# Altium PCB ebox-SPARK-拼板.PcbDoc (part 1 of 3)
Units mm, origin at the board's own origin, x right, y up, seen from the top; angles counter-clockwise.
Board outline 102 x 90 mm, 2 copper layers (Top Layer, Bottom Layer); 141 components, 68 nets, 621 pads, 146 vias.
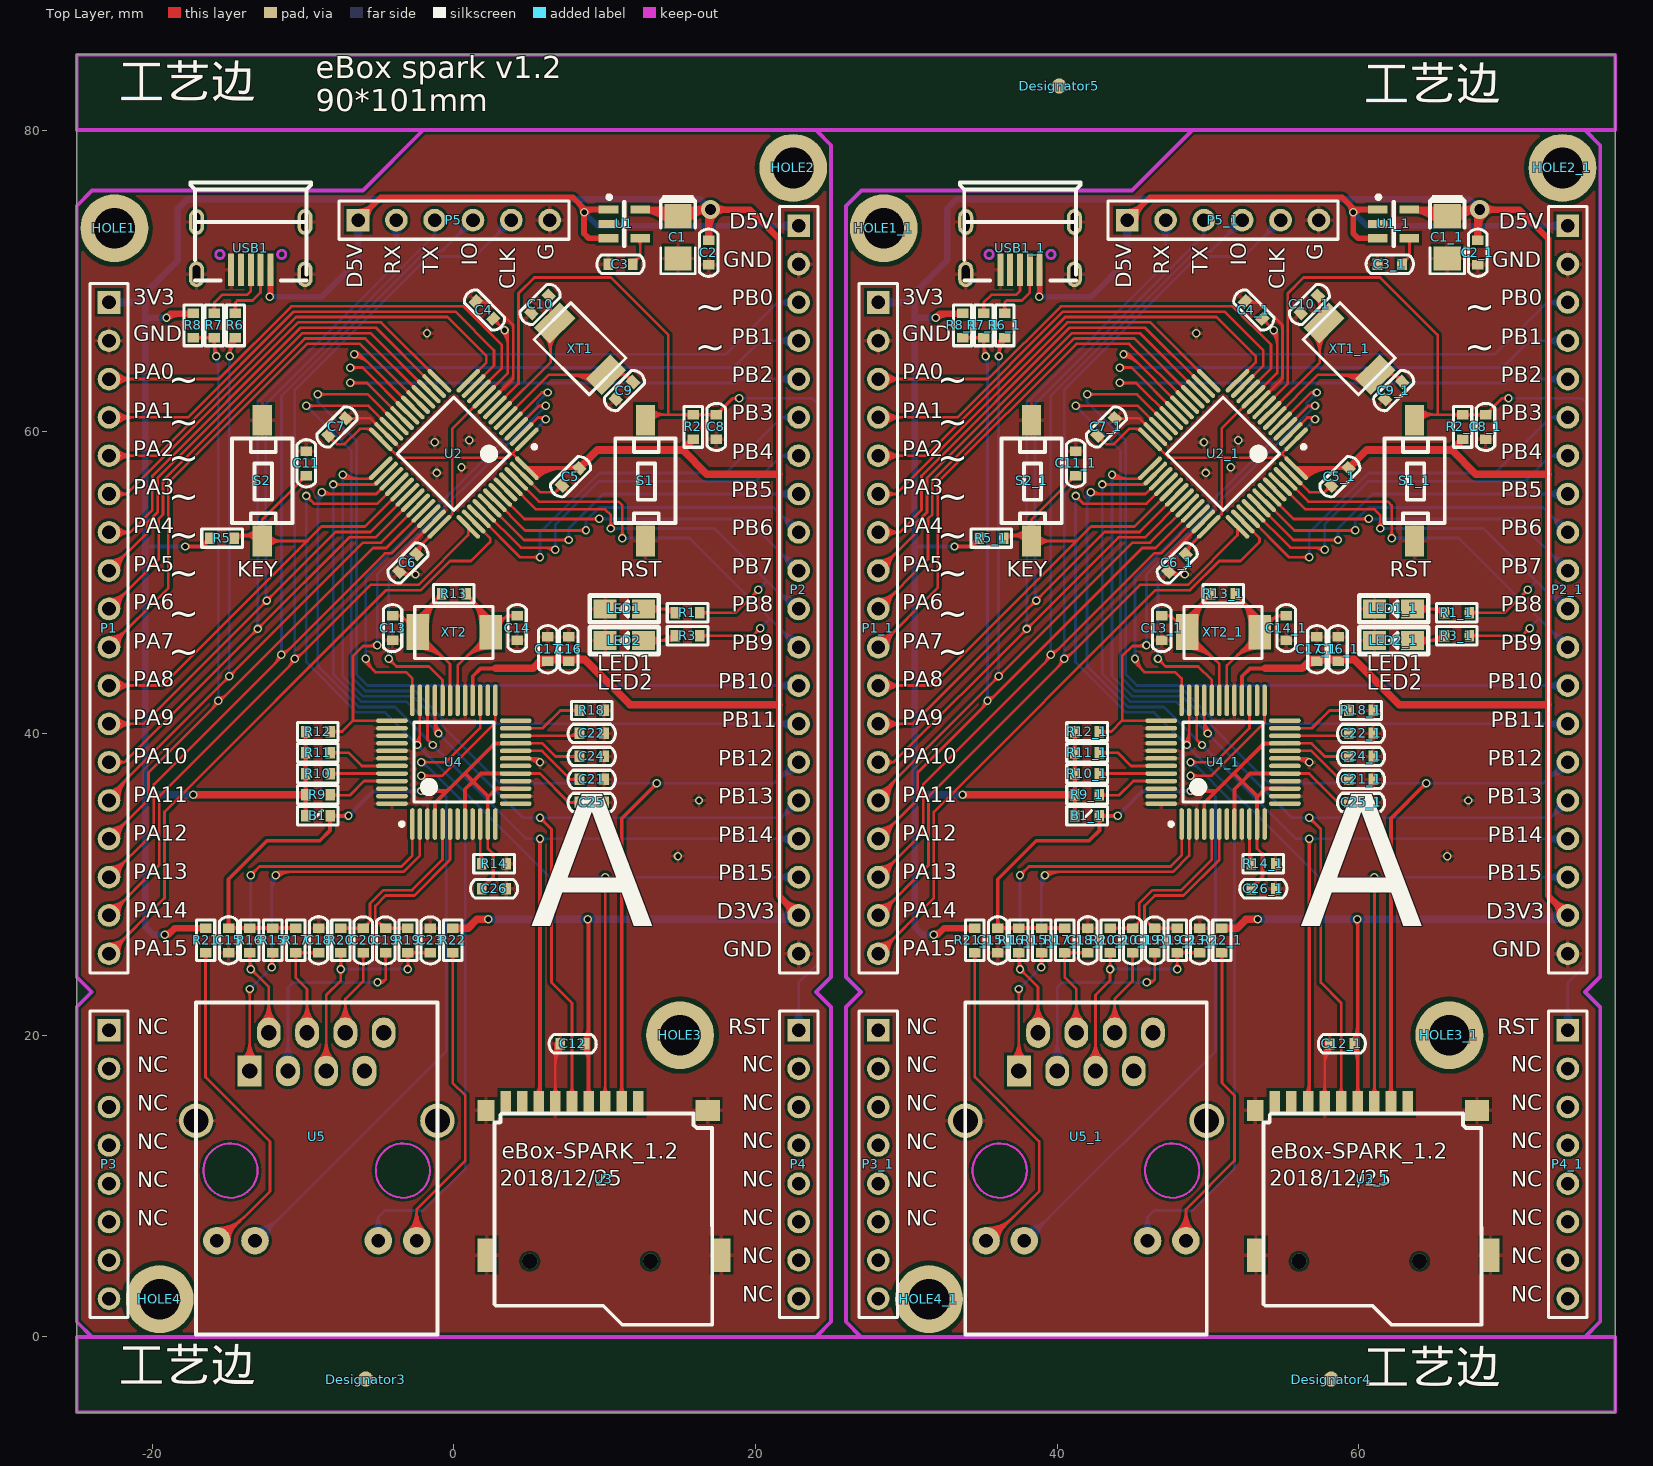
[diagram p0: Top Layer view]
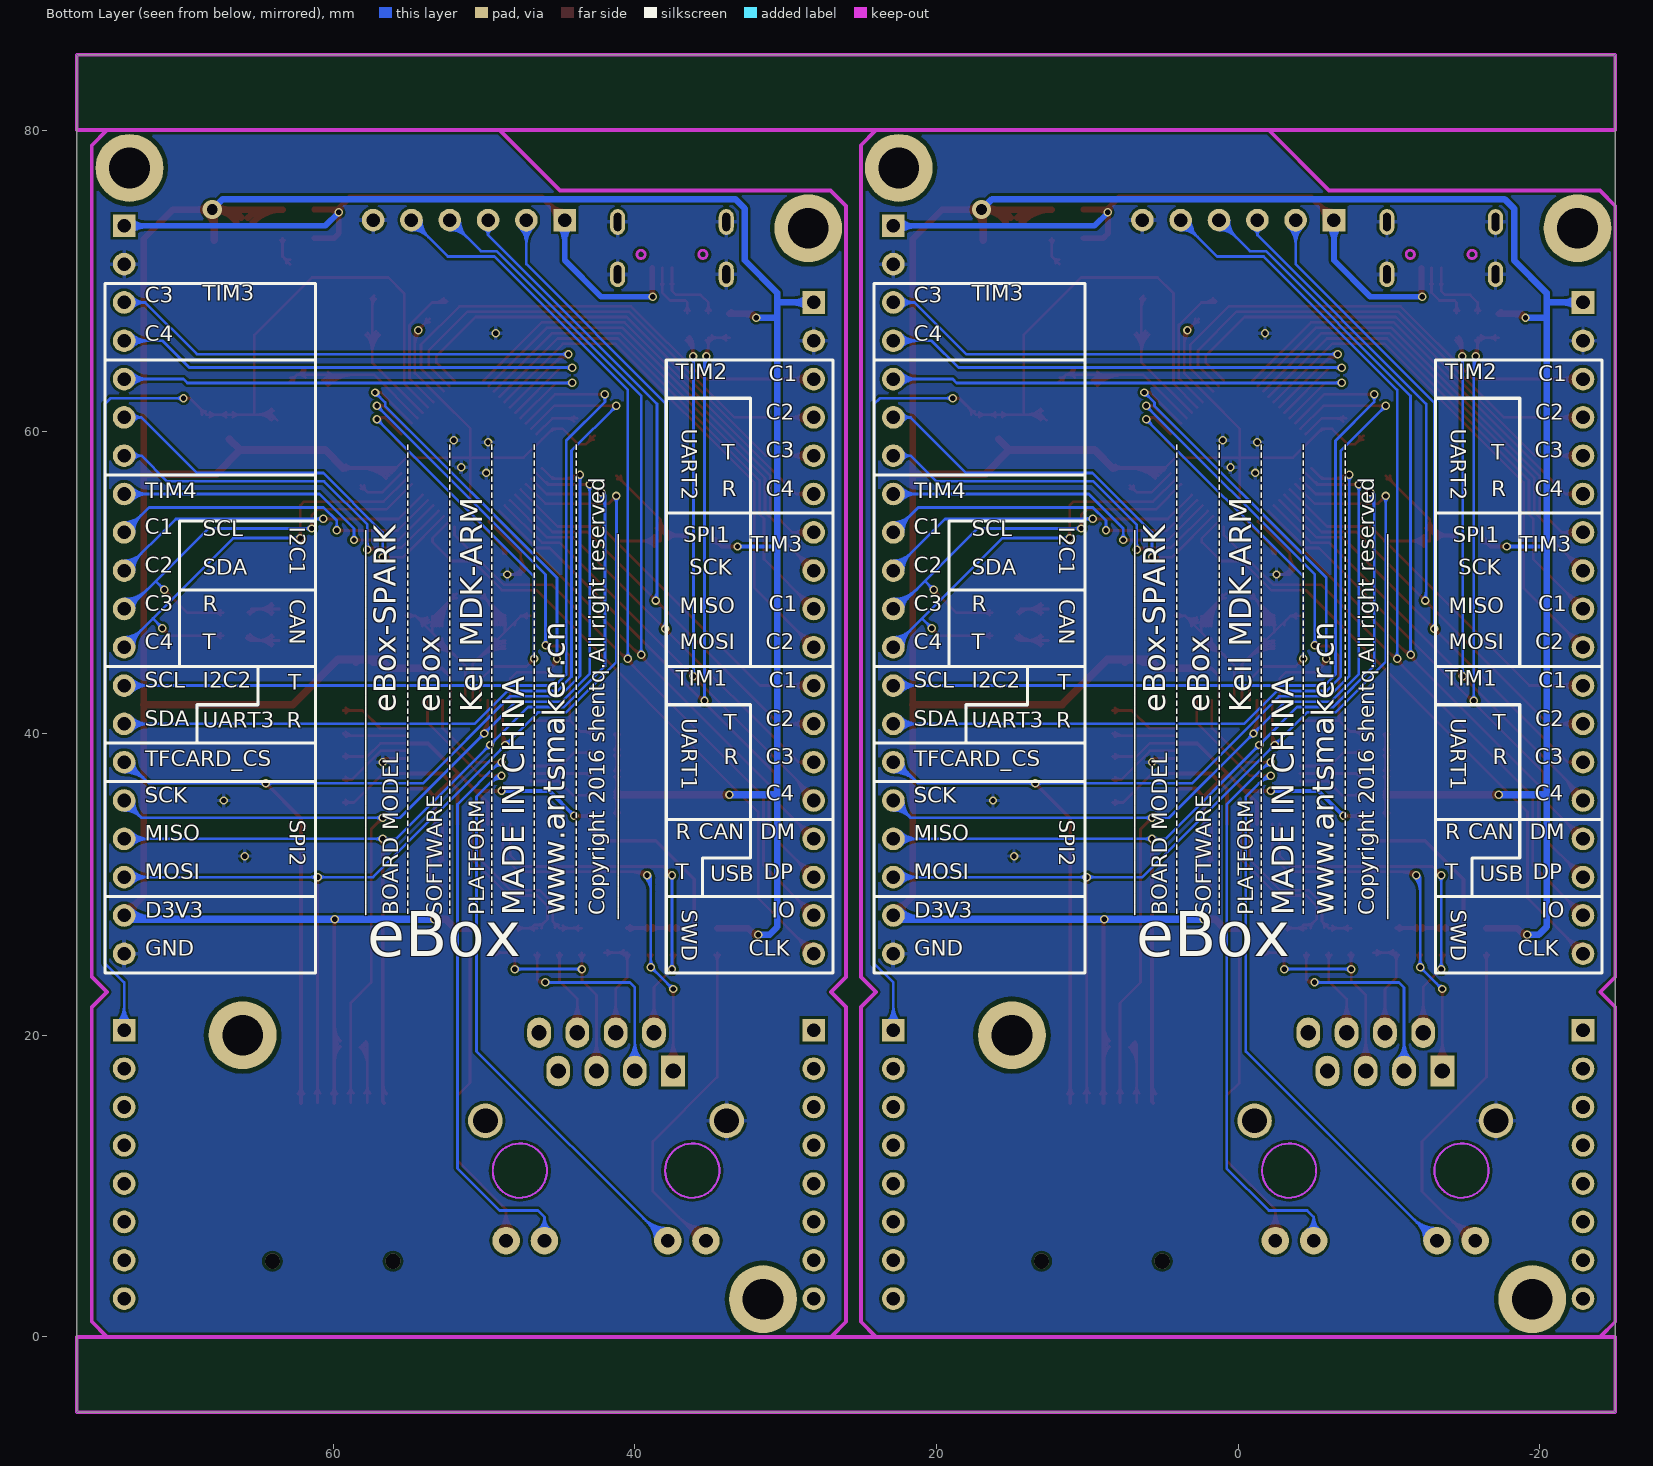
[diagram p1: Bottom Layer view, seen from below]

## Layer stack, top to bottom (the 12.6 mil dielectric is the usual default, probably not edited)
Top Layer: signal copper 0.0356
Dielectric: dielectric 0.32, FR-4, Dk 4.8
Bottom Layer: signal copper 0.0356

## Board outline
-25,85.003 77,85.003 77,-5 -25,-5

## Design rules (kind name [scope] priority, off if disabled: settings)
Clearance [All] p1: gap=0.178
ComponentClearance [All] p1: gap=0 collisioncheckmode=3 verticalgap=0 showdistances=FALSE
HoleSize [All] p1: absolutevalues=TRUE maxlimit=25.4 minlimit=0.025 maxpercent=80.000 minpercent=20.000
HoleToHoleClearance [All] p1: gap=0.178 allowstackedmicrovias=TRUE
MinimumSolderMaskSliver [All] p1: minsoldermaskwidth=0
PolygonConnect [All] p1: connectstyle=Relief reliefconductorwidth=0.254 reliefentries=4 polygonreliefangle="90 Angle"
RoomDefinition main_1.12 [InComponentClass('main_1.12')] p1: confinementstyle=ConfineIn formatcopy=TRUE lockcomponents=FALSE outline -109.836,-22.479 -59.036,-22.479 -59.036,2.921 -109.836,2.921
RoomDefinition U_W5500 [InComponentClass('U_W5500')] p2: confinementstyle=ConfineIn formatcopy=TRUE lockcomponents=FALSE outline -109.836,-22.479 -59.036,-22.479 -59.036,2.921 -109.836,2.921
RoomDefinition U_SDCARD [InComponentClass('U_SDCARD')] p3: confinementstyle=ConfineIn formatcopy=TRUE lockcomponents=FALSE outline -109.836,-22.479 -59.036,-22.479 -59.036,2.921 -109.836,2.921
RoomDefinition U_MCU [InComponentClass('U_MCU')] p4: confinementstyle=ConfineIn formatcopy=TRUE lockcomponents=FALSE outline -109.836,-22.479 -59.036,-22.479 -59.036,2.921 -109.836,2.921
RoutingVias [All] p1: holewidth=0.356 width=0.559 viastyle="Through Hole" minholewidth=0.356 minwidth=0.559 maxholewidth=7.112 maxwidth=12.7
SilkToSilkClearance [All] p1: silktosilkclearance=0
SilkscreenOverComponentPads [All] p1: minsilkscreentomaskgap=0
SolderMaskExpansion [All] p1: expansion=0.102
TestPointUsage [All] p1: valid=0 allowmultiple=FALSE
Testpoint [All] p1: side=15 testpointundercomponent=TRUE minsize=1.016 maxsize=2.54 preferedsize=1.524 minholesize=0 maxholesize=1.016 preferedholesize=0.813 testpointgrid=0.025 style=1023 order=0123456789
Width [All] p1: maxlimit=2.54 minlimit=0.178 preferedwidth=0.178
18 further rules are at their usual default settings.

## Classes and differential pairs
component class U_MCU: C1 C2 C3 C4 C5 C6 C7 C8 C9 C10 C11 LED1 LED2 P1 P2 P3 P4 P5 R1 R2 R3 R5 R6 R7 R8 S1 S2 T1 U1 U2 USB1 XT1
component class U_SDCARD: C12 U3
component class U_W5500: B1 C13 C14 C15 C16 C17 C18 C19 C20 C21 C22 C23 C24 C25 C26 R6 R7 R8 R9 R13 R14 R15 R16 R17 R18 R19 R20 R21 R22 R24 R25 R26 U4 U5 XT2
component class main_1.12: P6 P7 P8 P9

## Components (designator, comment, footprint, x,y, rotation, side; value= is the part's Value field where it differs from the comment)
B1 "BEAD" 0603L -9.017,34.544 r0 top
B1_1 "BEAD" 0603L 41.983,34.544 r0 top (schematic designator B1)
C1 "10UF" 3216C 14.859,74.295 r90 top
C1_1 "10UF" 3216C 65.859,74.295 r90 top (schematic designator C1)
C2 "104" 0603C 16.891,71.882 r90 top
C2_1 "104" 0603C 67.891,71.882 r90 top (schematic designator C2)
C3 "104" 0603C 11.049,71.12 r180 top
C3_1 "104" 0603C 62.049,71.12 r180 top (schematic designator C3)
C4 "104" 0603C 2.032,68.072 r315 top
C4_1 "104" 0603C 53.032,68.072 r315 top (schematic designator C4)
C5 "104" 0603C 7.747,57.023 r45 top
C5_1 "104" 0603C 58.747,57.023 r45 top (schematic designator C5)
C6 "104" 0603C -3.048,51.308 r225 top
C6_1 "104" 0603C 47.952,51.308 r225 top (schematic designator C6)
C7 "104" 0603C -7.747,60.325 r225 top
C7_1 "104" 0603C 43.253,60.325 r225 top (schematic designator C7)
C8 "104" 0603C 17.399,60.325 r270 top
C8_1 "104" 0603C 68.399,60.325 r270 top (schematic designator C8)
C9 "22P" 0603C 11.303,62.738 r225 top
C9_1 "22P" 0603C 62.303,62.738 r225 top (schematic designator C9)
C10 "22P" 0603C 5.715,68.453 r225 top
C10_1 "22P" 0603C 56.715,68.453 r225 top (schematic designator C10)
C11 "104" 0603C -9.779,57.912 r270 top
C11_1 "104" 0603C 41.221,57.912 r270 top (schematic designator C11)
C12 "104" 0603C 7.874,19.431 r180 top
C12_1 "104" 0603C 58.874,19.431 r180 top (schematic designator C12)
C13 "22P" 0603C -4.064,46.99 r90 top
C13_1 "22P" 0603C 46.936,46.99 r90 top (schematic designator C13)
C14 "22P" 0603C 4.191,46.99 r270 top
C14_1 "22P" 0603C 55.191,46.99 r270 top (schematic designator C14)
C15 "104" 0603C -14.935,26.289 r270 top
C15_1 "104" 0603C 36.065,26.289 r270 top (schematic designator C15)
C16 "104" 0603C 7.62,45.593 r90 top
C16_1 "104" 0603C 58.62,45.593 r90 top (schematic designator C16)
C17 "105" 0603C 6.223,45.593 r90 top
C17_1 "105" 0603C 57.223,45.593 r90 top (schematic designator C17)
C18 "104" 0603C -8.966,26.289 r270 top
C18_1 "104" 0603C 42.034,26.289 r270 top (schematic designator C18)
C19 "104" 0603C -4.521,26.289 r90 top
C19_1 "104" 0603C 46.479,26.289 r90 top (schematic designator C19)
C20 "104" 0603C -6.003,26.289 r90 top
C20_1 "104" 0603C 44.997,26.289 r90 top (schematic designator C20)
C21 "105" 0603C 9.144,36.957 r180 top
C21_1 "105" 0603C 60.144,36.957 r180 top (schematic designator C21)
C22 "104" 0603C 9.144,40.005 r180 top
C22_1 "104" 0603C 60.144,40.005 r180 top (schematic designator C22)
C23 "104" 0603C -1.558,26.289 r90 top
C23_1 "104" 0603C 49.442,26.289 r90 top (schematic designator C23)
C24 "104" 0603C 9.144,38.481 r180 top
C24_1 "104" 0603C 60.144,38.481 r180 top (schematic designator C24)
C25 "104" 0603C 9.144,35.433 r180 top
C25_1 "104" 0603C 60.144,35.433 r180 top (schematic designator C25)
C26 "104" 0603C 2.667,29.718 r180 top
C26_1 "104" 0603C 53.667,29.718 r180 top (schematic designator C26)
Designator3 "Comment" MARKER-C -5.842,-2.794 r0 top
Designator4 "Comment" MARKER-C 58.166,-2.794 r0 top
Designator5 "Comment" MARKER-C 40.132,82.931 r0 top
HOLE1 "HOLE" M2.5#1 -22.098,79.375 r90 top
HOLE1_1 "HOLE" M2.5#1 28.902,79.375 r90 top (schematic designator HOLE1)
HOLE2 "HOLE" M2.5#2 45.993,0.762 r90 top
HOLE2_1 "HOLE" M2.5#2 96.993,0.762 r90 top (schematic designator HOLE2)
HOLE3 "HOLE" M2.5#3 37.103,0.762 r90 top
HOLE3_1 "HOLE" M2.5#3 88.103,0.762 r90 top (schematic designator HOLE3)
HOLE4 "HOLE" M2.5#4 28.213,0.762 r90 top
HOLE4_1 "HOLE" M2.5#4 79.213,0.762 r90 top (schematic designator HOLE4)
LED1 "LED" 0805D 11.303,48.26 r180 top
LED1_1 "LED" 0805D 62.303,48.26 r180 top (schematic designator LED1)
LED2 "LED" 0805D 11.303,46.164 r180 top
LED2_1 "LED" 0805D 62.303,46.164 r180 top (schematic designator LED2)
P1 "Header 18" HDR1X18 -22.86,68.58 r270 top
P1_1 "Header 18" HDR1X18 28.14,68.58 r270 top (schematic designator P1)
P2 "Header 20" HDR1X20 22.86,73.66 r270 top
P2_1 "Header 20" HDR1X20 73.86,73.66 r270 top (schematic designator P2)
P3 "Header 8" HDR1X8 -22.86,20.32 r270 top
P3_1 "Header 8" HDR1X8 28.14,20.32 r270 top (schematic designator P3)
P4 "Header 8" HDR1X8 22.86,20.32 r270 top
P4_1 "Header 8" HDR1X8 73.86,20.32 r270 top (schematic designator P4)
P5 "SWD" HDR1X6 -6.35,74.041 r0 top
P5_1 "SWD" HDR1X6 44.65,74.041 r0 top (schematic designator P5)
R1 "1.5K" 0603R 15.494,48.006 r180 top
R1_1 "1.5K" 0603R 66.494,48.006 r180 top (schematic designator R1)
R2 "10K" 0603R 15.875,60.325 r90 top
R2_1 "10K" 0603R 66.875,60.325 r90 top (schematic designator R2)
R3 "1.5K" 0603R 15.494,46.482 r180 top
R3_1 "1.5K" 0603R 66.494,46.482 r180 top (schematic designator R3)
R5 "10K" 0603R -15.367,52.959 r0 top
R5_1 "10K" 0603R 35.633,52.959 r0 top (schematic designator R5)
R6 "22R" 0603R -14.478,67.056 r90 top
R6_1 "22R" 0603R 36.522,67.056 r90 top (schematic designator R6)
R7 "22R" 0603R -15.875,67.056 r90 top
R7_1 "22R" 0603R 35.125,67.056 r90 top (schematic designator R7)
R8 "1.5K" 0603R -17.272,67.056 r90 top
R8_1 "1.5K" 0603R 33.728,67.056 r90 top (schematic designator R8)
R9 "10K" 0603R -9.017,35.941 r180 top
R9_1 "10K" 0603R 41.983,35.941 r180 top (schematic designator R9)
R10 "10K" 0603R -9.017,37.338 r180 top
R10_1 "10K" 0603R 41.983,37.338 r180 top (schematic designator R10)
R11 "10K" 0603R -9.017,38.735 r180 top
R11_1 "10K" 0603R 41.983,38.735 r180 top (schematic designator R11)
R12 "10K" 0603R -9.017,40.132 r180 top
R12_1 "10K" 0603R 41.983,40.132 r180 top (schematic designator R12)
R13 "1M" 0603R 0,49.276 r180 top
R13_1 "1M" 0603R 51,49.276 r180 top (schematic designator R13)
R14 "12.4K%1" 0603R 2.667,31.369 r0 top
R14_1 "12.4K%1" 0603R 53.667,31.369 r0 top (schematic designator R14)
R15 "50R" 0603R -12.014,26.289 r90 top
R15_1 "50R" 0603R 38.986,26.289 r90 top (schematic designator R15)
R16 "50R" 0603R -13.538,26.289 r90 top
R16_1 "50R" 0603R 37.462,26.289 r90 top (schematic designator R16)
R17 "50R" 0603R -10.49,26.289 r90 top
R17_1 "50R" 0603R 40.51,26.289 r90 top (schematic designator R17)
R18 "10K" 0603R 9.144,41.529 r180 top
R18_1 "10K" 0603R 60.144,41.529 r180 top (schematic designator R18)
R19 "50R" 0603R -3.04,26.289 r270 top
R19_1 "50R" 0603R 47.96,26.289 r270 top (schematic designator R19)
R20 "50R" 0603R -7.485,26.289 r270 top
R20_1 "50R" 0603R 43.515,26.289 r270 top (schematic designator R20)
R21 "1.5K" 0603R -16.459,26.289 r270 top
R21_1 "1.5K" 0603R 34.541,26.289 r270 top (schematic designator R21)
R22 "1.5K" 0603R -0.076,26.289 r270 top
R22_1 "1.5K" 0603R 50.924,26.289 r270 top (schematic designator R22)
S1 "SW-BUTTON" SW-KEY 12.7,56.769 r90 top
S1_1 "SW-BUTTON" SW-KEY 63.7,56.769 r90 top (schematic designator S1)
S2 "SW-BUTTON" SW-KEY -12.7,56.769 r90 top locked
S2_1 "SW-BUTTON" SW-KEY 38.3,56.769 r90 top locked (schematic designator S2)
U1 "MIC5219" SOT23-5 11.303,73.787 r0 top
U1_1 "MIC5219" SOT23-5 62.303,73.787 r0 top (schematic designator U1)
U2 "STM32F103" LQFP48 0,58.547 r225 top
U2_1 "STM32F103" LQFP48 51,58.547 r225 top (schematic designator U2)
U3 "TFCard" TF-2 9.5,9.779 r270 top
U3_1 "TFCard" TF-2 60.5,9.779 r270 top (schematic designator U3)
U4 "W5500" LQFP48 0,38.1 r90 top locked
U4_1 "W5500" LQFP48 51,38.1 r90 top locked (schematic designator U4)
U5 "HR911105" HR911105A -9.5,6.731 r270 top locked
U5_1 "HR911105" HR911105A 41.5,6.731 r270 top locked (schematic designator U5)
USB1 "USB-Micro" USB-Micro-2 -13.462,73.914 r270 top
USB1_1 "USB-Micro" USB-Micro-2 37.538,73.914 r270 top (schematic designator USB1)
XT1 "8M" 5032 8.382,65.532 r135 top
XT1_1 "8M" 5032 59.382,65.532 r135 top (schematic designator XT1)
XT2 "25M" 5032 0,46.736 r180 top
XT2_1 "25M" 5032 51,46.736 r180 top (schematic designator XT2)

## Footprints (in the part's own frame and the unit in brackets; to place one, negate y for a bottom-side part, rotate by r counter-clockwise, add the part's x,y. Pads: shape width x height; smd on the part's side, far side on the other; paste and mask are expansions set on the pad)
0603C [mil]
  rect 25x30 smd: 1(-32,0) 2(32,0)
  silkscreen extent -62,-24 62,24, body extent -30,-16 33,16, height 12
0603L [mil]
  rect 25x30 smd: 1(-32,0) 2(32,0)
  silkscreen extent -53,-24 53,24, body extent -31,-16 32,16, height 24
0603R [mil]
  rect 25x30 smd: 1(-32,0) 2(32,0)
  silkscreen extent -53,-24 53,24, body extent -32,-15 30,16, height 12
0805D [mm]
  rect 1.524x1.25 smd: A(-1.27,0) K(1.27,0)
  silkscreen extent -2.29,-0.89 2.29,0.89, body extent -1.06,-0.64 0.96,0.62, height 1.1
3216C [mm] "A型"
  rect 1.6x1.8 smd: 1(0,0) 2(-2.8,0)
  silkscreen extent -3.81,-1.14 1.4,1.14, body extent -3.02,-0.8 0.18,0.8, height 1.6
5032 [mm]
  rect 1.5x2.3 smd: 1(-2.438,0.025)
  rect 1.5x2.4 smd: 2(2.388,0)
  silkscreen extent -2.59,-1.7 2.59,1.75
HDR1X6 [mm]
  rect 1.5x1.5 hole 0.9: 1(0,0)
  round 1.5 hole 0.9: 2(2.54,0) 3(5.08,0) 4(7.62,0) 5(10.16,0) 6(12.7,0)
  silkscreen extent -1.27,-1.27 13.97,1.27, body extent -1.27,-1.24 13.97,1.25, height 8.54
HDR1X8 [mm]
  rect 1.5x1.5 hole 0.9: 1(0,0)
  round 1.5 hole 0.9: 2(2.54,0) 3(5.08,0) 4(7.62,0) 5(10.16,0) 6(12.7,0) 7(15.24,0) 8(17.78,0)
  silkscreen extent -1.27,-1.27 19.05,1.27, body extent -1.24,-1.24 19.08,1.25, height 8.54
HDR1X18 [mm]
  rect 1.5x1.5 hole 0.9: 1(0,0)
  round 1.5 hole 0.9: 2(2.54,0) 3(5.08,0) 4(7.62,0) 5(10.16,0) 6(12.7,0) 7(15.24,0) 8(17.78,0) 9(20.32,0) 10(22.86,0) 11(25.4,0) 12(27.94,0) 13(30.48,0) 14(33.02,0) 15(35.56,0) 16(38.1,0) 17(40.64,0) 18(43.18,0)
  silkscreen extent -1.27,-1.27 44.45,1.27, body extent -1.24,-1.24 44.48,1.25, height 8.54
HDR1X20 [mm]
  rect 1.5x1.5 hole 0.9: 1(0,0)
  round 1.5 hole 0.9: 2(2.54,0) 3(5.08,0) 4(7.62,0) 5(10.16,0) 6(12.7,0) 7(15.24,0) 8(17.78,0) 9(20.32,0) 10(22.86,0) 11(25.4,0) 12(27.94,0) 13(30.48,0) 14(33.02,0) 15(35.56,0) 16(38.1,0) 17(40.64,0) 18(43.18,0) 19(45.72,0) 20(48.26,0)
  silkscreen extent -1.27,-1.27 49.53,1.27, body extent -1.24,-1.24 49.56,1.25, height 8.54
HR911105A [mil] "HR911105A"
  rect 80x62 hole 40: 1(-429,-159)
  oval 80x62 hole 40: 2(-529,-109) 3(-429,-59) 4(-529,-9) 5(-429,41) 6(-529,91) 7(-429,141) 8(-529,191)
  round 72 hole 36: 9(13.91,-244.63) 10(13.91,-145) 11(13.91,176.87) 12(13.91,277)
  round 90 hole 65: 13(-299.08,-298.76) 14(-299.08,331.16)
  Keep-Out Layer circle w5: c-169,241 r70.8
  Keep-Out Layer circle w5: c-169,-209 r70.8
  Multi-Layer circle w5: c-169,-209 r70.8
  Multi-Layer circle w5: c-169,241 r70.8
  silkscreen extent -608,-299 258,331
LQFP48 [mm]
  oval 2.1x0.3 smd: 1(-4.1,2.75) 2(-4.1,2.25) 3(-4.1,1.75) 4(-4.1,1.25) 5(-4.1,0.75) 6(-4.1,0.25) 7(-4.1,-0.25) 8(-4.1,-0.75) 9(-4.1,-1.25) 10(-4.1,-1.75) 11(-4.1,-2.25) 12(-4.1,-2.75) 25(4.1,-2.75) 26(4.1,-2.25) 27(4.1,-1.75) 28(4.1,-1.25) 29(4.1,-0.75) 30(4.1,-0.25) 31(4.1,0.25) 32(4.1,0.75) 33(4.1,1.25) 34(4.1,1.75) 35(4.1,2.25) 36(4.1,2.75)
  oval 0.3x2.1 smd: 13(-2.75,-4.1) 14(-2.25,-4.1) 15(-1.75,-4.1) 16(-1.25,-4.1) 17(-0.75,-4.1) 18(-0.25,-4.1) 19(0.25,-4.1) 20(0.75,-4.1) 21(1.25,-4.1) 22(1.75,-4.1) 23(2.25,-4.1) 24(2.75,-4.1) 37(2.75,4.1) 38(2.25,4.1) 39(1.75,4.1) 40(1.25,4.1) 41(0.75,4.1) 42(0.25,4.1) 43(-0.25,4.1) 44(-0.75,4.1) 45(-1.25,4.1) 46(-1.75,4.1) 47(-2.25,4.1) 48(-2.75,4.1)
  silkscreen extent -4.22,-2.65 2.65,3.57, body extent -4.5,-4.5 4.5,4.5, height 1.4
M2.5#1 [mm]
  round 4.5 hole 2.7: 0(-5.875,0.402)
M2.5#2 [mm]
  round 4.5 hole 2.7: 0(76.738,23.493)
M2.5#3 [mm]
  round 4.5 hole 2.7: 0(19.238,22.103)
M2.5#4 [mm]
  round 4.5 hole 2.7: 0(1.738,47.713)
MARKER-C [mm]
  round 1 smd paste-1.016 mask+0.5: 0(0,0)
  Top Layer pour cut-out: -1.109,0 -1.072,-0.287 -0.961,-0.555 -0.785,-0.785 -0.555,-0.961 -0.287,-1.072 0,-1.109 0,-1.109 0.287,-1.072 0.555,-0.961 0.785,-0.785 0.961,-0.555 1.072,-0.287 1.109,0 1.109,0 1.072,0.287 0.961,0.555 0.785,0.785 0.555,0.961 0.287,1.072 0,1.109 0,1.109 -0.287,1.072 -0.555,0.961 -0.785,0.785 -0.961,0.555 -1.072,0.287 -1.109,0
SOT23-5 [mm] "SOT23, 5-Leads, Body 3.0x2.6mm (max), Pitch 0.95mm, IPC Medium Density"
  rect 1.3x0.55 smd: 1(-1.051,0.95) 2(-1.051,0) 3(-1.051,-0.95) 4(1.051,-0.95) 5(1.051,0.95)
  silkscreen extent -1.12,-1.5 0.05,1.9, body extent -1.48,-1.45 1.32,1.45, height 1.45
SW-KEY [mm]
  rect 2.032x1.27 smd: 1(-4,0) 2(4,0)
  silkscreen extent -2.8,-2 2.8,2
TF-2 [mm]
  rect 1.4x1.6 smd: 0(-5.236,7.333)
  rect 1.4x1.1 smd: 0(-5.236,-7.367)
  rect 2.2x1.2 smd: 0(4.364,8.233) 0(4.364,-7.317)
  rect 1.6x0.7 smd: 1(-5.736,2.733) 2(-5.736,1.633) 3(-5.736,0.533) 4(-5.736,-0.567) 5(-5.736,-1.667) 6(-5.736,-2.767) 7(-5.736,-3.867) 8(-5.736,-4.967) 9(-5.736,-6.067)
  silkscreen extent -5.03,-6.81 8.98,7.63, body extent -6.41,-7.59 8.84,8.41, height 1.95
USB-Micro-2 [mm]
  oval 1.7x1 hole 0.5 slot 1.2 at 0 deg: 0(0,3.6) 0(0,-3.6) 0(3.47,3.6) 0(3.47,-3.6)
  rect 2.15x0.4 smd: 1(3.16,1.3) 2(3.16,0.65) 3(3.16,0) 4(3.16,-0.65) 5(3.16,-1.3)
  Keep-Out Layer circle w0.178: c2.15,-2.05 r0.275
  Keep-Out Layer circle w0.178: c2.15,2.05 r0.275
  silkscreen extent -2.62,-4 3.87,4, body extent -1.94,-4.4 3.66,4.4, height 2.74

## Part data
B1 B1_1: "磁珠"
C1 C1_1: library part CAP-T, "钽电容"
C2 C2_1 C3 C3_1 C4 C4_1 C5 C5_1 C6 C6_1 C7 C7_1 C8 C8_1 C9 C9_1 C10 C10_1 C11 C11_1 C12 C12_1 C13 C13_1 C14 C14_1 C15 C15_1 C16 C16_1 C17 C17_1 C18 C18_1 C19 C19_1 C20 C20_1 C21 C21_1 C22 C22_1 C23 C23_1 C24 C24_1 C25 C25_1 C26 C26_1: library part CAP, "普通小电容"
HOLE1 HOLE1_1 HOLE2 HOLE2_1 HOLE3 HOLE3_1 HOLE4 HOLE4_1: "standard screw"
P1 P1_1: "Header, 18-Pin"
P2 P2_1: "Header, 20-Pin"
P3 P3_1 P4 P4_1: "Header, 8-Pin"
P5 P5_1: "单片机端"
R1 R1_1 R2 R2_1 R3 R3_1 R5 R5_1 R6 R6_1 R7 R7_1 R8 R8_1 R9 R9_1 R10 R10_1 R11 R11_1 R12 R12_1 R13 R13_1 R14 R14_1 R15 R15_1 R16 R16_1 R17 R17_1 R18 R18_1 R19 R19_1 R20 R20_1 R21 R21_1 R22 R22_1: library part RES, "普通电阻"
U3 U3_1: library part TFCARD
USB1 USB1_1: "USB 1.1, Right Angle, SMT, A Type, Plug, 4 Position, Natural"
XT1 XT1_1 XT2 XT2_1: library part XT, "晶振"

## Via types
v1: diameter 0.559, hole 0.356, Top Layer to Bottom Layer, tented both sides, 140 vias
v2: diameter 1, hole 1, Top Layer to Bottom Layer, tented both sides, 4 vias
v3: diameter 1.27, hole 0.711, Top Layer to Bottom Layer, tented both sides, 2 vias

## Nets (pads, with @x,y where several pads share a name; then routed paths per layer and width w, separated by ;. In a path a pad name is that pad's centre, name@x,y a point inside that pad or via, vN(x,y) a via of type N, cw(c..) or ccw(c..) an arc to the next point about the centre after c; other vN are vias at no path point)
A3V3: B1.2 B1_1.2 C15.1 C15_1.1 C24.2 C24_1.2 C25.2 C25_1.2 C26.2 C26_1.2 R15.2 R15_1.2 R16.2 R16_1.2 R17.2 R17_1.2 U4.4 U4.8 U4.11 U4.15 U4.17 U4.21 U4_1.4 U4_1.8 U4_1.11 U4_1.15 U4_1.17 U4_1.21 | length 142.4
  Top Layer w0.178: U4.11@2.25,34 2.25,32.37 2.616,32.004 ; U4.17@4.1,37.35 5.703,37.35 7.62,35.433 C25.2@8.331,35.433 ; U4.21@4.1,39.35 5.872,39.35 6.741,38.481 C24.2@8.331,38.481 ; C25.2@8.17,35.271 ccw(c7.779,34.881) 7.779,35.433 ccw(c7.779,35.985) C25.2@8.17,35.595 ; C24.2@8.17,38.319 ccw(c7.779,37.929) 7.779,38.481 ccw(c7.779,39.033) C24.2@8.17,38.643 ; U4_1.11@53.25,34 53.25,32.37 53.616,32.004 ; U4_1.17@55.1,37.35 56.703,37.35 58.62,35.433 C25_1.2@59.331,35.433 ; U4_1.21@55.1,39.35 56.872,39.35 57.741,38.481 C24_1.2@59.331,38.481 ; C25_1.2@59.17,35.271 ccw(c58.779,34.881) 58.779,35.433 ccw(c58.779,35.985) C25_1.2@59.17,35.595 ; C24_1.2@59.17,38.319 ccw(c58.779,37.929) 58.779,38.481 ccw(c58.779,39.033) C24_1.2@59.17,38.643
  Top Layer w0.254: C15.1@-15.07,27.237 ccw(c-15.395,27.562) -14.935,27.562 ccw(c-14.475,27.562) C15.1@-14.8,27.237 ; C15.1@-14.737,26.967 cw(c-14.412,26.642) -14.412,27.102 cw(c-14.412,27.562) C15.1@-14.737,27.237 ; R16.2@-13.736,26.967 ccw(c-14.062,26.642) -14.062,27.102 ccw(c-14.062,27.562) R16.2@-13.736,27.237 ; R16.2@-13.34,26.967 cw(c-13.015,26.642) -13.015,27.102 cw(c-13.015,27.562) R16.2@-13.34,27.237 ; R15.2@-12.212,26.967 ccw(c-12.538,26.642) -12.538,27.102 ccw(c-12.538,27.562) R15.2@-12.212,27.237 ; R15.2@-11.816,26.967 cw(c-11.491,26.642) -11.491,27.102 cw(c-11.491,27.562) R15.2@-11.816,27.237 ; R17.2@-10.688,26.967 ccw(c-11.014,26.642) -11.014,27.102 ccw(c-11.014,27.562) R17.2@-10.688,27.237 ; R17.2@-10.49,27.102 R15.2@-12.014,27.102 R16.2@-13.538,27.102 C15.1@-14.935,27.102 -14.935,30.341 -12.383,32.893 -8.89,32.893 -8.204,33.579 B1.2@-8.204,34.544 v1(-6.985,34.544) ; B1.2@-8.339,34.346 cw(c-8.664,34.021) -8.204,34.021 cw(c-7.744,34.021) B1.2@-8.069,34.346 ; B1.2@-8.069,34.409 cw(c-7.744,34.084) -7.744,34.544 cw(c-7.744,35.004) B1.2@-8.069,34.679 ; v1@-7.093,34.436 ccw(c-7.353,34.176) -7.353,34.544 ccw(c-7.353,34.912) v1@-7.093,34.652 ; v1(-2.159,36.195) -0.508,36.195 ; v1@-2.051,36.087 cw(c-1.791,35.827) -1.791,36.195 cw(c-1.791,36.563) v1@-2.051,36.303 ; U4.4@-1.25,34 -1.25,35.389 0.73,37.37 ; U4.8@0.75,34 0.75,36.31 1.27,36.83 ; C26.2@1.854,29.718 2.616,30.48 2.616,32.004 ; C26.2@1.854,29.972 ccw(c1.854,30.585) 2.288,30.152 ; C26.2@2.045,29.781 cw(c2.351,29.781) C26.2@2.135,29.998 ; U4.11@2.25,34 2.25,35.778 2.822,36.35 U4.15@4.1,36.35 ; 2.25,35.85 1.27,36.83 ; U4.17@4.1,37.35 1.79,37.35 1.27,36.83 ; U4.21@4.1,39.35 2.711,39.35 0.73,37.37 ; C15_1.1@35.93,27.237 ccw(c35.605,27.562) 36.065,27.562 ccw(c36.525,27.562) C15_1.1@36.2,27.237 ; C15_1.1@36.263,26.967 cw(c36.588,26.642) 36.588,27.102 cw(c36.588,27.562) C15_1.1@36.263,27.237 ; R16_1.2@37.264,26.967 ccw(c36.938,26.642) 36.938,27.102 ccw(c36.938,27.562) R16_1.2@37.264,27.237 ; R16_1.2@37.66,26.967 cw(c37.985,26.642) 37.985,27.102 cw(c37.985,27.562) R16_1.2@37.66,27.237 ; R15_1.2@38.788,26.967 ccw(c38.462,26.642) 38.462,27.102 ccw(c38.462,27.562) R15_1.2@38.788,27.237 ; R15_1.2@39.184,26.967 cw(c39.509,26.642) 39.509,27.102 cw(c39.509,27.562) R15_1.2@39.184,27.237 ; R17_1.2@40.312,26.967 ccw(c39.986,26.642) 39.986,27.102 ccw(c39.986,27.562) R17_1.2@40.312,27.237 ; R17_1.2@40.51,27.102 R15_1.2@38.986,27.102 R16_1.2@37.462,27.102 C15_1.1@36.065,27.102 36.065,30.341 38.617,32.893 42.11,32.893 42.796,33.579 B1_1.2@42.796,34.544 v1(44.015,34.544) ; B1_1.2@42.661,34.346 cw(c42.336,34.021) 42.796,34.021 cw(c43.256,34.021) B1_1.2@42.931,34.346 ; B1_1.2@42.931,34.409 cw(c43.256,34.084) 43.256,34.544 cw(c43.256,35.004) B1_1.2@42.931,34.679 ; v1@43.907,34.436 ccw(c43.647,34.176) 43.647,34.544 ccw(c43.647,34.912) v1@43.907,34.652 ; v1(48.841,36.195) 50.492,36.195 ; v1@48.949,36.087 cw(c49.209,35.827) 49.209,36.195 cw(c49.209,36.563) v1@48.949,36.303 ; U4_1.4@49.75,34 49.75,35.389 51.73,37.37 ; U4_1.8@51.75,34 51.75,36.31 52.27,36.83 ; C26_1.2@52.854,29.718 53.616,30.48 53.616,32.004 ; C26_1.2@52.854,29.972 ccw(c52.854,30.585) 53.288,30.152 ; C26_1.2@53.045,29.781 cw(c53.351,29.781) C26_1.2@53.135,29.998 ; U4_1.11@53.25,34 53.25,35.778 53.822,36.35 U4_1.15@55.1,36.35 ; 53.25,35.85 52.27,36.83 ; U4_1.17@55.1,37.35 52.79,37.35 52.27,36.83 ; U4_1.21@55.1,39.35 53.711,39.35 51.73,37.37 ; 0.73,37.37 1.27,36.83 ; 51.73,37.37 52.27,36.83
  Bottom Layer w0.254: v1(-6.985,34.544) -5.334,36.195 v1(-2.159,36.195) ; v1@-6.985,34.696 ccw(c-6.985,35.064) -6.725,34.804 ccw(c-6.465,34.544) v1@-6.833,34.544 ; v1@-2.267,36.087 ccw(c-2.527,35.827) -2.527,36.195 ccw(c-2.527,36.563) v1@-2.267,36.303 ; v1(44.015,34.544) 45.666,36.195 v1(48.841,36.195) ; v1@44.015,34.696 ccw(c44.015,35.064) 44.275,34.804 ccw(c44.535,34.544) v1@44.167,34.544 ; v1@48.733,36.087 ccw(c48.473,35.827) 48.473,36.195 ccw(c48.473,36.563) v1@48.733,36.303
ACTLED: U4.27 U4_1.27 U5.11 U5_1.11 | length 97.2
  Top Layer w0.178: v1(-2.159,38.1) -0.508,38.1 1.75,40.358 U4.27@1.75,42.2 ; v1@-2.024,37.965 cw(c-1.699,37.64) -1.699,38.1 cw(c-1.699,38.56) v1@-2.024,38.235 ; v1(48.841,38.1) 50.492,38.1 52.75,40.358 U4_1.27@52.75,42.2 ; v1@48.976,37.965 cw(c49.301,37.64) 49.301,38.1 cw(c49.301,38.56) v1@48.976,38.235
  Bottom Layer w0.178: U5.11@-5.475,7.058 ccw(c-6.085,7.946) -5.008,7.946 ; U5.11@-5.374,6.911 ccw(c-5.853,7.608) -5.008,7.608 ccw(c-4.162,7.608) U5.11@-4.641,6.911 ; U5.11@-5.008,6.378 -5.008,7.946 ; U5.11@-4.54,7.058 cw(c-3.93,7.946) -5.008,7.946 ; v1@-2.159,37.91 cw(c-2.159,37.143) -1.617,37.685 ; v1(-2.159,38.1) -2.032,38.1 0.762,35.306 0.762,11.176 -2.032,8.382 -4.572,8.382 -5.008,7.946 ; U5_1.11@45.525,7.058 ccw(c44.915,7.946) 45.992,7.946 ; U5_1.11@45.626,6.911 ccw(c45.147,7.608) 45.992,7.608 ccw(c46.838,7.608) U5_1.11@46.359,6.911 ; U5_1.11@45.992,6.378 45.992,7.946 ; U5_1.11@46.46,7.058 cw(c47.07,7.946) 45.992,7.946 ; v1@48.841,37.91 cw(c48.841,37.143) 49.383,37.685 ; v1(48.841,38.1) 48.968,38.1 51.762,35.306 51.762,11.176 48.968,8.382 46.428,8.382 45.992,7.946
D3V3: B1.1 B1_1.1 C1.1 C1_1.1 C2.2 C2_1.2 C4.2 C4_1.2 C5.2 C5_1.2 C6.1 C6_1.1 C7.2 C7_1.2 C12.1 C12_1.1 C16.1 C16_1.1 C17.1 C17_1.1 P1.1 P1_1.1 P2.19 P2_1.19 R2.1 R2_1.1 R5.1 R5_1.1 R8.2 R8_1.2 R9.2 R9_1.2 R10.2 R10_1.2 R11.2 R11_1.2 R12.2 R12_1.2 R21.1 R21_1.1 R22.1 R22_1.1 U1.5 U1_1.5 U2.1 U2.9 U2.24 U2.36 U2.48 U2_1.1 U2_1.9 U2_1.24 U2_1.36 U2_1.48 U3.4 U3_1.4 U4.28 U4_1.28 | length 659.3
  Top Layer w0.178: C7.2@-8.322,59.75 -7.753,59.182 -7.239,59.182 -6.223,60.198 -5.54,60.198 U2.24@-4.844,59.502 -3.634,58.292 -0.099,58.292 ; C7.2@-8.277,59.477 cw(c-8.277,58.925) -7.887,59.315 cw(c-7.496,59.705) C7.2@-8.048,59.705 ; -5.772,60.198 cw(c-5.772,59.846) U2.24@-5.523,60.095 ; C6.1@-2.473,51.883 -2.473,52.185 U2.36@-0.955,53.703 -0.099,54.559 -0.099,58.292 ; C6.1@-2.467,51.928 cw(c-1.833,51.928) -2.281,52.376 ; C6.1@-2.29,51.928 cw(c-1.226,51.928) -1.978,52.68 ; C4.2@2.607,67.269 cw(c2.607,66.717) 2.997,67.107 cw(c3.387,67.497) C4.2@2.835,67.497 ; C4.2@2.607,67.497 v1(3.362,66.742) 3.581,66.523 3.581,63.896 U2.9@2.015,62.33 -0.099,60.216 -0.099,58.292 ; v1@3.172,66.742 ccw(c2.712,66.742) 3.037,67.067 ccw(c3.362,67.392) v1@3.362,66.932 ; v1@3.228,66.607 cw(c2.374,65.753) 3.581,65.753 ; v1@3.353,66.733 cw(c2.803,66.182) 3.581,66.182 ; 3.912,58.524 U2.48@4.844,57.592 ; U2.48@4.144,58.292 U2.48@4.844,57.592 ; U2.1@4.844,59.502 3.634,58.292 -0.099,58.292 ; U2.48@4.849,57.598 U2.48@4.844,57.592 ; C7_1.2@42.678,59.75 43.247,59.182 43.761,59.182 44.777,60.198 45.46,60.198 U2_1.24@46.156,59.502 47.366,58.292 50.901,58.292 ; C7_1.2@42.723,59.477 cw(c42.723,58.925) 43.113,59.315 cw(c43.504,59.705) C7_1.2@42.952,59.705 ; 45.228,60.198 cw(c45.228,59.846) U2_1.24@45.477,60.095 ; C6_1.1@48.527,51.883 48.527,52.185 U2_1.36@50.045,53.703 50.901,54.559 50.901,58.292 ; C6_1.1@48.533,51.928 cw(c49.167,51.928) 48.719,52.376 ; C6_1.1@48.71,51.928 cw(c49.774,51.928) 49.022,52.68 ; C4_1.2@53.607,67.269 cw(c53.607,66.717) 53.997,67.107 cw(c54.387,67.497) C4_1.2@53.835,67.497 ; C4_1.2@53.607,67.497 v1(54.362,66.742) 54.581,66.523 54.581,63.896 U2_1.9@53.015,62.33 50.901,60.216 50.901,58.292 ; v1@54.172,66.742 ccw(c53.712,66.742) 54.037,67.067 ccw(c54.362,67.392) v1@54.362,66.932 ; v1@54.228,66.607 cw(c53.374,65.753) 54.581,65.753 ; v1@54.353,66.733 cw(c53.803,66.182) 54.581,66.182 ; 54.912,58.524 U2_1.48@55.844,57.592 ; U2_1.48@55.144,58.292 U2_1.48@55.844,57.592 ; U2_1.1@55.844,59.502 54.634,58.292 50.901,58.292 ; U2_1.48@55.849,57.598 U2_1.48@55.844,57.592
  Top Layer w0.254: v1(-17.805,52.4) -16.739,52.4 R5.1@-16.18,52.959 ; v1@-17.698,52.292 cw(c-17.437,52.032) -17.437,52.4 cw(c-17.437,52.768) v1@-17.698,52.508 ; -16.613,52.525 cw(c-16.18,52.092) R5.1@-16.18,52.705 ; R5.1@-16.46,52.679 ccw(c-16.677,52.895) R5.1@-16.37,52.895 ; B1.1@-9.965,34.742 ccw(c-10.29,35.067) -9.83,35.067 ccw(c-9.37,35.067) B1.1@-9.695,34.742 ; R9.2@-9.965,35.743 cw(c-10.29,35.418) -9.83,35.418 cw(c-9.37,35.418) R9.2@-9.695,35.743 ; R9.2@-9.965,36.139 ccw(c-10.29,36.464) -9.83,36.464 ccw(c-9.37,36.464) R9.2@-9.695,36.139 ; R10.2@-9.965,37.14 cw(c-10.29,36.815) -9.83,36.815 cw(c-9.37,36.815) R10.2@-9.695,37.14 ; R10.2@-9.965,37.536 ccw(c-10.29,37.861) -9.83,37.861 ccw(c-9.37,37.861) R10.2@-9.695,37.536 ; R11.2@-9.965,38.537 cw(c-10.29,38.212) -9.83,38.212 cw(c-9.37,38.212) R11.2@-9.695,38.537 ; R11.2@-9.965,38.933 ccw(c-10.29,39.258) -9.83,39.258 ccw(c-9.37,39.258) R11.2@-9.695,38.933 ; R12.2@-9.965,39.934 cw(c-10.29,39.609) -9.83,39.609 cw(c-9.37,39.609) R12.2@-9.695,39.934 ; B1.1@-9.83,34.544 -9.83,35.909 -9.83,37.274 -9.83,38.64 R12.2@-9.83,40.005 ; U4.28@1.25,42.2 1.25,43.795 1.778,44.323 2.794,44.323 ; U2.48@4.849,57.598 C5.2@8.322,57.598 ; U2.48@4.958,57.479 cw(c5.245,57.191) 5.245,57.598 ; U2.48@5.137,57.299 cw(c5.858,56.578) 5.858,57.598 ; U2.48@5.317,57.119 cw(c6.472,55.964) 6.472,57.598 ; U2.48@5.496,56.94 cw(c7.085,55.351) 7.085,57.598 ; 7.709,57.598 ccw(c7.709,58.211) C5.2@8.142,57.777 ; C5.2@7.925,57.598 cw(c7.925,57.291) C5.2@8.142,57.508 ; C12.1@8.552,19.233 cw(c7.634,18.314) 8.933,18.314 ; C12.1@8.552,19.629 ccw(c7.634,20.548) 8.933,20.548 ; C12.1@8.732,19.412 cw(c8.247,18.927) 8.933,18.927 ; C12.1@8.732,19.45 ccw(c8.247,19.935) 8.933,19.935 ; U3.4@8.775,16.122 ccw(c8.394,16.503) 8.933,16.503 ccw(c9.471,16.503) U3.4@9.09,16.122 ; v1@8.782,27.578 cw(c8.419,27.215) 8.933,27.215 ; v1(8.89,27.686) 8.933,27.643 U3.4@8.933,15.515 ; v1(33.195,52.4) 34.261,52.4 R5_1.1@34.82,52.959 ; v1@33.302,52.292 cw(c33.563,52.032) 33.563,52.4 cw(c33.563,52.768) v1@33.302,52.508 ; 34.387,52.525 cw(c34.82,52.092) R5_1.1@34.82,52.705 ; R5_1.1@34.54,52.679 ccw(c34.323,52.895) R5_1.1@34.63,52.895 ; B1_1.1@41.035,34.742 ccw(c40.71,35.067) 41.17,35.067 ccw(c41.63,35.067) B1_1.1@41.305,34.742 ; R9_1.2@41.035,35.743 cw(c40.71,35.418) 41.17,35.418 cw(c41.63,35.418) R9_1.2@41.305,35.743 ; R9_1.2@41.035,36.139 ccw(c40.71,36.464) 41.17,36.464 ccw(c41.63,36.464) R9_1.2@41.305,36.139 ; R10_1.2@41.035,37.14 cw(c40.71,36.815) 41.17,36.815 cw(c41.63,36.815) R10_1.2@41.305,37.14 ; R10_1.2@41.035,37.536 ccw(c40.71,37.861) 41.17,37.861 ccw(c41.63,37.861) R10_1.2@41.305,37.536 ; R11_1.2@41.035,38.537 cw(c40.71,38.212) 41.17,38.212 cw(c41.63,38.212) R11_1.2@41.305,38.537 ; R11_1.2@41.035,38.933 ccw(c40.71,39.258) 41.17,39.258 ccw(c41.63,39.258) R11_1.2@41.305,38.933 ; R12_1.2@41.035,39.934 cw(c40.71,39.609) 41.17,39.609 cw(c41.63,39.609) R12_1.2@41.305,39.934 ; B1_1.1@41.17,34.544 41.17,35.909 41.17,37.274 41.17,38.64 R12_1.2@41.17,40.005 ; U4_1.28@52.25,42.2 52.25,43.795 52.778,44.323 53.794,44.323 ; U2_1.48@55.849,57.598 C5_1.2@59.322,57.598 ; U2_1.48@55.958,57.479 cw(c56.245,57.191) 56.245,57.598 ; U2_1.48@56.137,57.299 cw(c56.858,56.578) 56.858,57.598 ; U2_1.48@56.317,57.119 cw(c57.472,55.964) 57.472,57.598 ; U2_1.48@56.496,56.94 cw(c58.085,55.351) 58.085,57.598 ; 58.709,57.598 ccw(c58.709,58.211) C5_1.2@59.142,57.777 ; C5_1.2@58.925,57.598 cw(c58.925,57.291) C5_1.2@59.142,57.508 ; C12_1.1@59.552,19.233 cw(c58.634,18.314) 59.933,18.314 ; C12_1.1@59.552,19.629 ccw(c58.634,20.548) 59.933,20.548 ; C12_1.1@59.732,19.412 cw(c59.247,18.927) 59.933,18.927 ; C12_1.1@59.732,19.45 ccw(c59.247,19.935) 59.933,19.935 ; U3_1.4@59.775,16.122 ccw(c59.394,16.503) 59.933,16.503 ccw(c60.471,16.503) U3_1.4@60.09,16.122 ; v1@59.782,27.578 cw(c59.419,27.215) 59.933,27.215 ; v1(59.89,27.686) 59.933,27.643 U3_1.4@59.933,15.515
  Top Layer w0.432: v1(-19.177,26.67) -18.923,26.67 -18.491,27.102 R21.1@-16.459,27.102 ; v1@-19.177,26.733 ccw(c-19.177,27.5) -18.635,26.958 ; v1(-19.05,67.564) -18.796,67.818 R8.2@-17.272,67.818 ; v1@-19.005,67.519 cw(c-18.283,66.797) -18.283,67.818 ; -17.703,67.818 ccw(c-17.703,68.237) R8.2@-17.407,67.941 ; U1.5@12.354,74.737 v3(17.018,74.737) ; U1.5@12.354,74.737 cw(c12.354,71.989) C1.1@14.337,73.891 ; 13.366,74.737 cw(c13.366,72.96) C1.1@14.649,74.19 ; C1.1@15.081,74.203 cw(c16.151,73.396) 16.151,74.737 ; C1.1@15.425,73.943 cw(c17.018,72.742) v3@17.018,74.737 ; v3@16.722,74.441 ccw(c16.006,73.725) 16.006,74.737 ccw(c16.006,75.749) v3@16.722,75.033 ; v3@17.314,74.441 cw(c18.03,73.725) 18.03,74.737 cw(c18.03,75.749) v3@17.314,75.033 ; P2.19@22.326,27.94 ccw(c21.036,27.94) 21.948,28.852 ccw(c22.86,29.764) P2.19@22.86,28.474 ; P2.19@22.86,27.94 21.565,29.235 21.565,41.91 21.565,57.201 21.565,72.796 19.624,74.737 v3(17.018,74.737) ; v1(31.823,26.67) 32.077,26.67 32.509,27.102 R21_1.1@34.541,27.102 ; v1@31.823,26.733 ccw(c31.823,27.5) 32.365,26.958 ; v1(31.95,67.564) 32.204,67.818 R8_1.2@33.728,67.818 ; v1@31.995,67.519 cw(c32.717,66.797) 32.717,67.818 ; 33.297,67.818 ccw(c33.297,68.237) R8_1.2@33.593,67.941 ; 64.366,74.737 cw(c64.366,72.96) C1_1.1@65.649,74.19 ; C1_1.1@65.337,73.891 ccw(c63.354,71.989) U1_1.5@63.354,74.737 v3(68.018,74.737) 70.624,74.737 72.565,72.796 72.565,57.201 72.565,41.91 72.565,29.235 P2_1.19@73.86,27.94 ; C1_1.1@66.081,74.203 cw(c67.151,73.396) 67.151,74.737 ; C1_1.1@66.425,73.943 cw(c68.018,72.742) v3(68.018,74.737) ; v3@67.722,74.441 ccw(c67.006,73.725) 67.006,74.737 ccw(c67.006,75.749) v3@67.722,75.033 ; v3@68.314,74.441 cw(c69.03,73.725) 69.03,74.737 cw(c69.03,75.749) v3@68.314,75.033 ; P2_1.19@73.326,27.94 ccw(c72.036,27.94) 72.948,28.852 ccw(c73.86,29.764) P2_1.19@73.86,28.474
  Top Layer w0.508: v1(-17.272,35.941) R9.2@-9.83,35.941 ; R22.1@-0.076,27.102 0.94,27.102 1.524,27.686 v1(2.286,27.686) ; 2.794,44.323 5.258,44.323 5.842,44.907 8.687,44.907 11.684,41.91 21.565,41.91 ; 5.292,44.357 cw(c6.159,43.49) C17.1@6.159,44.717 ; C17.1@6.331,44.735 cw(c6.746,44.32) 6.746,44.907 ; 7.097,44.907 cw(c7.097,44.32) C16.1@7.512,44.735 ; C5.2@8.322,57.598 9.525,58.801 15.164,58.801 ; R2.1@15.875,59.512 15.164,58.801 ; C2.2@16.891,72.695 16.891,74.61 v3(17.018,74.737) ; 16.891,73.511 cw(c18.244,73.511) v3@17.287,74.468 ; 21.565,57.201 16.764,57.201 15.164,58.801 ; v1(33.728,35.941) R9_1.2@41.17,35.941 ; R22_1.1@50.924,27.102 51.94,27.102 52.524,27.686 v1(53.286,27.686) ; 53.794,44.323 56.258,44.323 56.842,44.907 59.687,44.907 62.684,41.91 72.565,41.91 ; 56.292,44.357 cw(c57.159,43.49) C17_1.1@57.159,44.717 ; C17_1.1@57.331,44.735 cw(c57.746,44.32) 57.746,44.907 ; 58.097,44.907 cw(c58.097,44.32) C16_1.1@58.512,44.735 ; C5_1.2@59.322,57.598 60.525,58.801 66.164,58.801 ; R2_1.1@66.875,59.512 66.164,58.801 ; C2_1.2@67.891,72.695 67.891,74.61 v3(68.018,74.737) ; 67.891,73.511 cw(c69.244,73.511) v3@68.287,74.468 ; 72.565,57.201 67.764,57.201 66.164,58.801
  Bottom Layer w0.254: -20.422,52.4 v1(-17.805,52.4) ; v1@-17.913,52.292 ccw(c-18.173,52.032) -18.173,52.4 ccw(c-18.173,52.768) v1@-17.913,52.508 ; 30.578,52.4 v1(33.195,52.4) ; v1@33.087,52.292 ccw(c32.827,52.032) 32.827,52.4 ccw(c32.827,52.768) v1@33.087,52.508
  Bottom Layer w0.432: P1.1@-22.86,68.58 -20.447,68.58 ; P1.1@-22.482,68.202 cw(c-21.571,67.291) -21.571,68.58 cw(c-21.571,69.869) P1.1@-22.482,68.958 ; -20.447,31.496 -20.447,31.75 ; v1(-19.177,26.67) -19.939,26.67 -20.447,27.178 -20.447,31.75 ; v1(-19.05,67.564) -20.447,67.564 ; v3@17.018,74.887 v3(17.018,74.737) 16.317,75.438 -17.653,75.438 -18.288,74.803 -18.288,71.374 -20.447,69.215 -20.447,68.58 ; P1_1.1@28.14,68.58 30.553,68.58 ; P1_1.1@28.518,68.202 cw(c29.429,67.291) 29.429,68.58 cw(c29.429,69.869) P1_1.1@28.518,68.958 ; 30.553,31.496 30.553,31.75 ; v1(31.823,26.67) 31.061,26.67 30.553,27.178 30.553,31.75 ; v1(31.95,67.564) 30.553,67.564 ; v3@68.018,74.887 v3(68.018,74.737) 67.317,75.438 33.347,75.438 32.712,74.803 32.712,71.374 30.553,69.215 30.553,68.58 ; -20.447,31.75 -20.447,35.941 -20.447,67.564 ; -20.447,67.564 -20.447,68.58 ; 30.553,31.75 30.553,35.941 30.553,67.564 ; 30.553,67.564 30.553,68.58
  Bottom Layer w0.508: -20.447,35.941 v1(-17.272,35.941) ; v1(2.286,27.686) 22.606,27.686 P2.19@22.86,27.94 ; 21.049,27.686 ccw(c21.049,29.751) P2.19@22.509,28.291 ; 30.553,35.941 v1(33.728,35.941) ; v1(53.286,27.686) 73.606,27.686 P2_1.19@73.86,27.94 ; 72.049,27.686 ccw(c72.049,29.751) P2_1.19@73.509,28.291
D5V: P2.1 P2_1.1 P5.1 P5_1.1 U1.1 U1.3 U1_1.1 U1_1.3 USB1.1 USB1_1.1 | length 109.9
  Top Layer w0.381: v1@-12.255,69.024 ccw(c-12.479,69.248) -12.162,69.248 ; v1(-12.192,68.961) -12.162,68.991 USB1.1@-12.162,70.754 USB1.1@-12.162,70.881 ; P5.1@-6.35,74.041 -4.851,75.54 7.899,75.54 8.636,74.803 v1(8.636,74.549) ; P5.1@-6.35,74.6 ccw(c-6.35,75.951) -5.395,74.996 ccw(c-4.44,74.041) P5.1@-5.791,74.041 ; 8.305,75.134 cw(c7.719,74.549) v1@8.547,74.549 ; v1@8.699,74.486 cw(c9.304,73.881) 9.304,74.737 ; U1.3@10.252,72.837 8.951,72.837 8.636,73.152 v1(8.636,74.549) ; U1.1@10.252,74.737 8.824,74.737 v1(8.636,74.549) ; v1@38.745,69.024 ccw(c38.521,69.248) 38.838,69.248 ; v1(38.808,68.961) 38.838,68.991 USB1_1.1@38.838,70.754 USB1_1.1@38.838,70.881 ; P5_1.1@44.65,74.041 46.149,75.54 58.899,75.54 59.636,74.803 v1(59.636,74.549) ; P5_1.1@44.65,74.6 ccw(c44.65,75.951) 45.605,74.996 ccw(c46.56,74.041) P5_1.1@45.209,74.041 ; 59.305,75.134 cw(c58.719,74.549) v1@59.547,74.549 ; v1@59.699,74.486 cw(c60.304,73.881) 60.304,74.737 ; U1_1.3@61.252,72.837 59.951,72.837 59.636,73.152 v1(59.636,74.549) ; U1_1.1@61.252,74.737 59.824,74.737 v1(59.636,74.549)
  Bottom Layer w0.381: v1(-12.192,68.961) -8.763,68.961 -6.35,71.374 P5.1@-6.35,74.041 ; P5.1@-6.746,73.645 cw(c-7.701,72.69) -6.35,72.69 cw(c-4.999,72.69) P5.1@-5.954,73.645 ; v1(8.636,74.549) 9.525,73.66 P2.1@22.86,73.66 ; P2.1@22.464,73.264 ccw(c21.509,72.309) 21.509,73.66 ccw(c21.509,75.011) P2.1@22.464,74.056 ; v1(38.808,68.961) 42.237,68.961 44.65,71.374 P5_1.1@44.65,74.041 ; P5_1.1@44.254,73.645 cw(c43.299,72.69) 44.65,72.69 cw(c46.001,72.69) P5_1.1@45.046,73.645 ; v1(59.636,74.549) 60.525,73.66 P2_1.1@73.86,73.66 ; P2_1.1@73.464,73.264 ccw(c72.509,72.309) 72.509,73.66 ccw(c72.509,75.011) P2_1.1@73.464,74.056
GND: C1.2 C1_1.2 C2.1 C2_1.1 C3.2 C3_1.2 C4.1 C4_1.1 C5.1 C5_1.1 C6.2 C6_1.2 C7.1 C7_1.1 C8.2 C8_1.2 C9.2 C9_1.2 C10.2 C10_1.2 C11.1 C11_1.1 C12.2 C12_1.2 C13.1 C13_1.1 C14.2 C14_1.2 C15.2 C15_1.2 C16.2 C16_1.2 C17.2 C17_1.2 C18.1 C18_1.1 C21.1 C21_1.1 C22.1 C22_1.1 C23.2 C23_1.2 C24.1 C24_1.1 C25.1 C25_1.1 C26.1 C26_1.1 LED1.K LED1_1.K LED2.K LED2_1.K P1.2 P1_1.2 P2.2 P2.20 P2_1.2 P2_1.20 P5.6 P5_1.6 R14.2 R14_1.2 R18.1 R18_1.1 S1.1 S1_1.1 S2.2 S2_1.2 U1.2 U1_1.2 U2.8 U2.23 U2.35 U2.44 U2.47 U2_1.8 U2_1.23 U2_1.35 U2_1.44 U2_1.47 U3.0 U3.6 U3_1.0 U3_1.6 U4.3 U4.9 U4.14 U4.16 U4.19 U4.29 U4.38 U4.39 U4.40 U4.41 U4.42 U4.48 U4_1.3 U4_1.9 U4_1.14 U4_1.16 U4_1.19 U4_1.29 U4_1.38 U4_1.39 U4_1.40 U4_1.41 U4_1.42 U4_1.48 U5.13 U5_1.13 USB1.0 USB1.5 USB1_1.0 USB1_1.5 | length 79.3
  Top Layer w0.178: C7.1@-7.172,60.9 -5.535,60.9 U2.23@-4.49,59.855 ; C7.1@-6.966,60.693 cw(c-6.467,60.195) -6.467,60.9 ; C7.1@-6.966,61.016 ccw(c-6.684,61.298) -6.684,60.9 ; C6.2@-3.829,50.94 ccw(c-4.796,51.906) -3.429,51.906 ; C6.2@-3.704,50.814 ccw(c-4.366,51.477) -3.429,51.477 ; C6.2@-3.623,50.733 -3.429,50.927 -3.429,51.936 U2.35@-1.308,54.057 ; C6.2@-3.578,50.688 ccw(c-3.937,51.048) -3.429,51.048 ; C6.2@-3.542,50.724 ccw(c-3.111,51.155) -3.111,50.546 ; C6.2@-3.435,50.546 v1(-2.54,50.546) ; C6.2@-3.416,50.85 ccw(c-2.682,51.584) v1@-2.682,50.546 ; v1@-2.675,50.411 ccw(c-3,50.086) -3,50.546 ccw(c-3,51.006) v1@-2.675,50.681 ; C4.1@1.457,68.647 1.524,68.58 2.44,68.58 3.937,67.083 3.937,63.545 U2.8@2.369,61.976 ; C4.1@1.538,68.728 ccw(c1.894,69.084) 1.894,68.58 ; C4.1@1.664,68.853 ccw(c2.324,69.513) 2.324,68.58 ; U4.19@4.1,38.35 5.465,38.35 v1(5.715,38.1) ; U2.47@4.49,57.239 5.722,56.007 6.731,56.007 C5.1@7.172,56.448 ; U4.19@4.652,38.35 cw(c4.652,37.037) v1@5.58,37.965 ; U4.19@5.081,38.35 cw(c5.081,37.466) v1@5.706,38.091 ; 5.51,38.35 cw(c5.51,37.895) v1@5.832,38.217 ; U3.6@6.548,16.149 ccw(c6.102,16.595) 6.733,16.595 ccw(c7.363,16.595) U3.6@6.917,16.149 ; U3.6@6.733,15.515 6.733,19.229 C12.2@6.934,19.431 ; 6.733,18.022 cw(c8.406,18.022) C12.2@7.223,19.206 ; 6.733,18.452 cw(c7.977,18.452) C12.2@7.097,19.332 ; 6.733,18.881 cw(c7.548,18.881) C12.2@6.971,19.457 ; 6.733,19.31 cw(c7.119,19.31) C12.2@6.846,19.583 ; C5.1@6.944,56.448 cw(c6.392,56.448) 6.782,56.058 cw(c7.172,55.668) C5.1@7.172,56.22 ; C7_1.1@43.828,60.9 45.465,60.9 U2_1.23@46.51,59.855 ; C7_1.1@44.034,60.693 cw(c44.533,60.195) 44.533,60.9 ; C7_1.1@44.034,61.016 ccw(c44.316,61.298) 44.316,60.9 ; C6_1.2@47.171,50.94 ccw(c46.204,51.906) 47.571,51.906 ; C6_1.2@47.296,50.814 ccw(c46.634,51.477) 47.571,51.477 ; C6_1.2@47.377,50.733 47.571,50.927 47.571,51.936 U2_1.35@49.692,54.057 ; C6_1.2@47.422,50.688 ccw(c47.063,51.048) 47.571,51.048 ; C6_1.2@47.458,50.724 ccw(c47.888,51.155) 47.888,50.546 ; C6_1.2@47.565,50.546 v1(48.46,50.546) ; C6_1.2@47.584,50.85 ccw(c48.318,51.584) v1@48.318,50.546 ; v1@48.325,50.411 ccw(c48,50.086) 48,50.546 ccw(c48,51.006) v1@48.325,50.681 ; C4_1.1@52.457,68.647 52.524,68.58 53.44,68.58 54.937,67.083 54.937,63.545 U2_1.8@53.369,61.976 ; C4_1.1@52.538,68.728 ccw(c52.894,69.084) 52.894,68.58 ; C4_1.1@52.664,68.853 ccw(c53.324,69.513) 53.324,68.58 ; U4_1.19@55.1,38.35 56.465,38.35 v1(56.715,38.1) ; U2_1.47@55.49,57.239 56.722,56.007 57.731,56.007 C5_1.1@58.172,56.448 ; U4_1.19@55.652,38.35 cw(c55.652,37.037) v1@56.58,37.965 ; U4_1.19@56.081,38.35 cw(c56.081,37.466) v1@56.706,38.091 ; 56.51,38.35 cw(c56.51,37.895) v1@56.832,38.217 ; U3_1.6@57.548,16.149 ccw(c57.102,16.595) 57.733,16.595 ccw(c58.363,16.595) U3_1.6@57.917,16.149 ; U3_1.6@57.733,15.515 57.733,19.229 C12_1.2@57.934,19.431 ; 57.733,18.022 cw(c59.406,18.022) C12_1.2@58.223,19.206 ; 57.733,18.452 cw(c58.977,18.452) C12_1.2@58.097,19.332 ; 57.733,18.881 cw(c58.548,18.881) C12_1.2@57.971,19.457 ; 57.733,19.31 cw(c58.119,19.31) C12_1.2@57.846,19.583 ; C5_1.1@57.944,56.448 cw(c57.392,56.448) 57.782,56.058 cw(c58.172,55.668) C5_1.1@58.172,56.22
  other v1: 14.859,31.877 65.859,31.877 16.256,35.56 67.256,35.56 -1.143,57.277 49.857,57.277 0.508,57.658 51.508,57.658 -1.27,59.309 49.73,59.309 1.016,59.436 52.016,59.436 -1.778,66.548 49.222,66.548
LINKLED: U4.25 U4_1.25 U5.10 U5_1.10 | length 110.2
  Top Layer w0.178: v1(-2.159,37.211) -0.762,37.211 2.75,40.723 U4.25@2.75,42.2 ; v1@-2.024,37.076 cw(c-1.699,36.751) -1.699,37.211 cw(c-1.699,37.671) v1@-2.024,37.346 ; v1(48.841,37.211) 50.238,37.211 53.75,40.723 U4_1.25@53.75,42.2 ; v1@48.976,37.076 cw(c49.301,36.751) 49.301,37.211 cw(c49.301,37.671) v1@48.976,37.346
  Bottom Layer w0.178: U5.10@-13.183,6.378 -13.053,6.378 -0.508,18.923 -0.508,35.814 -1.372,36.678 ; U5.10@-13.183,6.67 ccw(c-13.183,7.688) -12.463,6.968 ; U5.10@-13.183,6.848 ccw(c-13.183,8.295) -12.16,7.271 ; U5.10@-13.183,7.025 ccw(c-13.183,8.902) -11.856,7.575 ; U5.10@-13.183,7.203 ccw(c-13.183,9.509) -11.553,7.878 ; U5.10@-12.713,6.378 cw(c-11.892,6.378) -12.472,6.959 ; U5.10@-12.535,6.378 cw(c-11.285,6.378) -12.169,7.262 ; U5.10@-12.357,6.378 cw(c-10.677,6.378) -11.865,7.566 ; v1@-2.159,37.02 cw(c-2.159,35.947) -1.4,36.706 ; v1@-2.159,37.198 cw(c-2.159,36.554) -1.704,37.01 ; v1(-2.159,37.211) -1.905,37.211 -1.372,36.678 ; -1.372,36.703 -1.372,36.678 ; U5_1.10@37.817,6.378 37.947,6.378 50.492,18.923 50.492,35.814 49.628,36.678 ; U5_1.10@37.817,6.67 ccw(c37.817,7.688) 38.537,6.968 ; U5_1.10@37.817,6.848 ccw(c37.817,8.295) 38.84,7.271 ; U5_1.10@37.817,7.025 ccw(c37.817,8.902) 39.144,7.575 ; U5_1.10@37.817,7.203 ccw(c37.817,9.509) 39.447,7.878 ; U5_1.10@38.287,6.378 cw(c39.108,6.378) 38.528,6.959 ; U5_1.10@38.465,6.378 cw(c39.715,6.378) 38.831,7.262 ; U5_1.10@38.643,6.378 cw(c40.323,6.378) 39.135,7.566 ; v1@48.841,37.02 cw(c48.841,35.947) 49.6,36.706 ; v1@48.841,37.198 cw(c48.841,36.554) 49.296,37.01 ; v1(48.841,37.211) 49.095,37.211 49.628,36.678 ; 49.628,36.703 49.628,36.678
MISO: P2.17 P2_1.17 U2.27 U2_1.27 U3.7 U3_1.7 U4.34 U4_1.34 | length 171.3
  Top Layer w0.178: v1(-8.763,56.007) -8.636,55.88 -5.142,55.88 U2.27@-4.137,56.885 ; v1@-8.754,56.016 ccw(c-8.426,56.344) -8.426,55.88 ; v1@-8.628,56.142 ccw(c-7.996,56.774) -7.996,55.88 ; U4.34@-1.75,42.2 -1.75,39.596 v1(-1.397,39.243) ; v1(42.237,56.007) 42.364,55.88 45.858,55.88 U2_1.27@46.863,56.885 ; v1@42.246,56.016 ccw(c42.574,56.344) 42.574,55.88 ; v1@42.372,56.142 ccw(c43.004,56.774) 43.004,55.88 ; U4_1.34@49.25,42.2 49.25,39.596 v1(49.603,39.243)
  Top Layer w0.254: U3.7@5.475,16.122 ccw(c4.895,16.702) 5.715,16.702 ; v1@5.607,32.912 cw(c5.347,32.652) 5.715,32.652 cw(c6.083,32.652) v1@5.823,32.912 ; U3.7@5.633,15.515 5.715,15.597 v1(5.715,33.02) ; U3_1.7@56.475,16.122 ccw(c55.895,16.702) 56.715,16.702 ; v1@56.607,32.912 cw(c56.347,32.652) 56.715,32.652 cw(c57.083,32.652) v1@56.823,32.912 ; U3_1.7@56.633,15.515 56.715,15.597 v1(56.715,33.02)
  Bottom Layer w0.178: -9.017,54.934 cw(c-7.69,54.934) v1@-8.628,55.872 ; -9.017,55.363 cw(c-8.119,55.363) v1@-8.754,55.998 ; -9.017,55.792 cw(c-8.548,55.792) v1@-8.88,56.124 ; v1(-8.763,56.007) -9.017,55.753 -9.017,44.47 -6.304,41.758 -3.912,41.758 v1(-1.397,39.243) 4.826,33.02 P2.17@22.86,33.02 ; v1@-1.587,39.243 ccw(c-2.047,39.243) -1.722,39.568 ccw(c-1.397,39.893) v1@-1.397,39.433 ; v1@-1.397,39.052 cw(c-1.397,38.593) -1.072,38.918 cw(c-0.747,39.243) v1@-1.207,39.243 ; v1@5.58,32.885 ccw(c5.255,32.56) 5.255,33.02 ccw(c5.255,33.48) v1@5.58,33.155 ; v1@5.85,32.885 cw(c6.175,32.56) 6.175,33.02 cw(c6.175,33.48) v1@5.85,33.155 ; P2.17@22.393,32.553 ccw(c21.264,31.424) 21.264,33.02 ccw(c21.264,34.616) P2.17@22.393,33.487 ; P2.17@22.518,32.678 ccw(c21.693,31.853) 21.693,33.02 ccw(c21.693,34.187) P2.17@22.518,33.362 ; 41.983,54.934 cw(c43.31,54.934) v1@42.372,55.872 ; 41.983,55.363 cw(c42.881,55.363) v1@42.246,55.998 ; 41.983,55.792 cw(c42.452,55.792) v1@42.12,56.124 ; v1(42.237,56.007) 41.983,55.753 41.983,44.47 44.696,41.758 47.088,41.758 v1(49.603,39.243) 55.826,33.02 P2_1.17@73.86,33.02 ; v1@49.412,39.243 ccw(c48.953,39.243) 49.278,39.568 ccw(c49.603,39.893) v1@49.603,39.433 ; v1@49.603,39.052 cw(c49.603,38.593) 49.928,38.918 cw(c50.253,39.243) v1@49.793,39.243 ; v1@56.58,32.885 ccw(c56.255,32.56) 56.255,33.02 ccw(c56.255,33.48) v1@56.58,33.155 ; v1@56.85,32.885 cw(c57.175,32.56) 57.175,33.02 cw(c57.175,33.48) v1@56.85,33.155 ; P2_1.17@73.393,32.553 ccw(c72.264,31.424) 72.264,33.02 ccw(c72.264,34.616) P2_1.17@73.393,33.487 ; P2_1.17@73.518,32.678 ccw(c72.693,31.853) 72.693,33.02 ccw(c72.693,34.187) P2_1.17@73.518,33.362
MOSI: P2.18 P2_1.18 U2.28 U2_1.28 U3.3 U3_1.3 U4.35 U4_1.35 | length 171.9
  Top Layer w0.178: v1@-9.779,55.562 cw(c-9.779,55.103) -9.454,55.428 cw(c-9.129,55.753) v1@-9.589,55.753 ; v1(-9.779,55.753) -9.271,55.245 -5.07,55.245 U2.28@-3.783,56.532 ; v1@-2.548,39.378 ccw(c-3.266,40.096) -2.25,40.096 ; v1@-2.422,39.252 ccw(c-2.837,39.667) -2.25,39.667 ; v1(-2.413,39.243) -2.25,39.406 U4.35@-2.25,42.2 ; U3.3@9.848,16.149 ccw(c9.402,16.595) 10.033,16.595 ccw(c10.663,16.595) U3.3@10.217,16.149 ; v1@9.898,30.345 cw(c9.574,30.021) 10.033,30.021 ; U3.3@10.033,15.515 v1@10.033,30.48 ; 10.033,30.019 cw(c10.494,30.019) v1@10.168,30.345 ; v1@41.221,55.562 cw(c41.221,55.103) 41.546,55.428 cw(c41.871,55.753) v1@41.411,55.753 ; v1(41.221,55.753) 41.729,55.245 45.93,55.245 U2_1.28@47.217,56.532 ; v1@48.452,39.378 ccw(c47.734,40.096) 48.75,40.096 ; v1@48.578,39.252 ccw(c48.163,39.667) 48.75,39.667 ; v1(48.587,39.243) 48.75,39.406 U4_1.35@48.75,42.2 ; U3_1.3@60.848,16.149 ccw(c60.402,16.595) 61.033,16.595 ccw(c61.663,16.595) U3_1.3@61.217,16.149 ; v1@60.898,30.345 cw(c60.574,30.021) 61.033,30.021 ; U3_1.3@61.033,15.515 v1(61.033,30.48) ; 61.033,30.019 cw(c61.494,30.019) v1@61.168,30.345
  Bottom Layer w0.178: v1@-9.914,55.618 cw(c-10.239,55.293) -9.779,55.293 cw(c-9.319,55.293) v1@-9.644,55.618 ; v1(-9.779,55.753) -9.779,44.73 -6.451,41.402 -4.572,41.402 v1(-2.413,39.243) 6.35,30.48 P2.18@22.86,30.48 ; v1@-2.603,39.243 ccw(c-3.063,39.243) -2.738,39.568 ccw(c-2.413,39.893) v1@-2.413,39.433 ; v1@-2.413,39.052 cw(c-2.413,38.593) -2.088,38.918 cw(c-1.763,39.243) v1@-2.223,39.243 ; v1@9.898,30.345 ccw(c9.573,30.02) 9.573,30.48 ccw(c9.573,30.94) v1@9.898,30.615 ; v1@10.168,30.345 cw(c10.493,30.02) 10.493,30.48 cw(c10.493,30.94) v1@10.168,30.615 ; P2.18@22.393,30.013 ccw(c21.264,28.884) 21.264,30.48 ccw(c21.264,32.076) P2.18@22.393,30.947 ; P2.18@22.518,30.138 ccw(c21.693,29.313) 21.693,30.48 ccw(c21.693,31.647) P2.18@22.518,30.822 ; v1@41.086,55.618 cw(c40.761,55.293) 41.221,55.293 cw(c41.681,55.293) v1@41.356,55.618 ; v1(41.221,55.753) 41.221,44.73 44.549,41.402 46.428,41.402 v1(48.587,39.243) 57.35,30.48 P2_1.18@73.86,30.48 ; v1@48.396,39.243 ccw(c47.937,39.243) 48.262,39.568 ccw(c48.587,39.893) v1@48.587,39.433 ; v1@48.587,39.052 cw(c48.587,38.593) 48.912,38.918 cw(c49.237,39.243) v1@48.777,39.243 ; v1@60.898,30.345 ccw(c60.573,30.02) 60.573,30.48 ccw(c60.573,30.94) v1@60.898,30.615 ; v1@61.168,30.345 cw(c61.493,30.02) 61.493,30.48 cw(c61.493,30.94) v1@61.168,30.615 ; P2_1.18@73.393,30.013 ccw(c72.264,28.884) 72.264,30.48 ccw(c72.264,32.076) P2_1.18@73.393,30.947 ; P2_1.18@73.518,30.138 ccw(c72.693,29.313) 72.693,30.48 ccw(c72.693,31.647) P2_1.18@73.518,30.822
  other v1: 10.033,30.48
NetC3_1: C3.1 C3_1.1 U1.4 U1_1.4 | length 7
  Top Layer w0.178: C3.1@11.862,71.12 12.354,71.612 ; C3.1@11.864,71.412 ccw(c11.871,72.095) 12.354,71.612 ; C3.1@12.09,71.183 cw(c12.489,71.183) 12.207,71.465 ; U1.4@12.222,72.705 cw(c11.905,72.388) 12.354,72.388 cw(c12.803,72.388) U1.4@12.485,72.705 ; U1.4@12.354,72.837 12.354,71.612 ; C3_1.1@62.862,71.12 63.354,71.612 ; C3_1.1@62.864,71.412 ccw(c62.871,72.095) 63.354,71.612 ; C3_1.1@63.09,71.183 cw(c63.489,71.183) 63.207,71.465 ; U1_1.4@63.222,72.705 cw(c62.905,72.388) 63.354,72.388 cw(c63.803,72.388) U1_1.4@63.485,72.705 ; U1_1.4@63.354,72.837 63.354,71.612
